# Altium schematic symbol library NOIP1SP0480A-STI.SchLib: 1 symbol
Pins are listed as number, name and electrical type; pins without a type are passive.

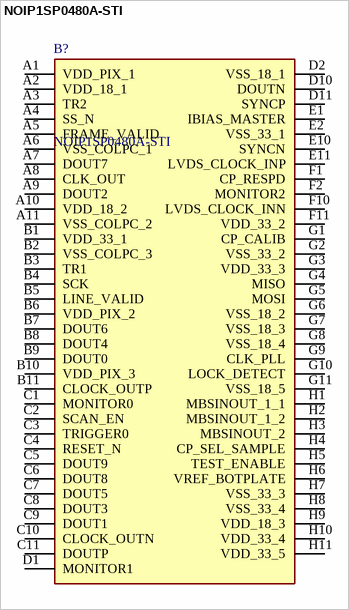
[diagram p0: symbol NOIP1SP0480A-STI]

## NOIP1SP0480A-STI
designator B?
Image Sensors PYTHON480 1/3.6 BW_ CRA; Manufacturer_Name: onsemi; Geometry.Height: 0.75mm
footprint NOIP1SP0480ASTI
pins: A1 VDD_PIX_1, A2 VDD_18_1, A3 TR2, A4 SS_N, A5 FRAME_VALID, A6 VSS_COLPC_1, A7 DOUT7, A8 CLK_OUT, A9 DOUT2, A10 VDD_18_2, A11 VSS_COLPC_2, B1 VDD_33_1, B2 VSS_COLPC_3, B3 TR1, B4 SCK, B5 LINE_VALID, B6 VDD_PIX_2, B7 DOUT6, B8 DOUT4, B9 DOUT0, B10 VDD_PIX_3, B11 CLOCK_OUTP, C1 MONITOR0, C2 SCAN_EN, C3 TRIGGER0, C4 RESET_N, C5 DOUT9, C6 DOUT8, C7 DOUT5, C8 DOUT3, C9 DOUT1, C10 CLOCK_OUTN, C11 DOUTP, D1 MONITOR1, D2 VSS_18_1, D10 DOUTN, D11 SYNCP, E1 IBIAS_MASTER, E2 VSS_33_1, E10 SYNCN, E11 LVDS_CLOCK_INP, F1 CP_RESPD, F2 MONITOR2, F10 LVDS_CLOCK_INN, F11 VDD_33_2, G1 CP_CALIB, G2 VSS_33_2, G3 VDD_33_3, G4 MISO, G5 MOSI, G6 VSS_18_2, G7 VSS_18_3, G8 VSS_18_4, G9 CLK_PLL, G10 LOCK_DETECT, G11 VSS_18_5, H1 MBSINOUT_1_1, H2 MBSINOUT_1_2, H3 MBSINOUT_2, H4 CP_SEL_SAMPLE, H5 TEST_ENABLE, H6 VREF_BOTPLATE, H7 VSS_33_3, H8 VSS_33_4, H9 VDD_18_3, H10 VDD_33_4, H11 VDD_33_5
